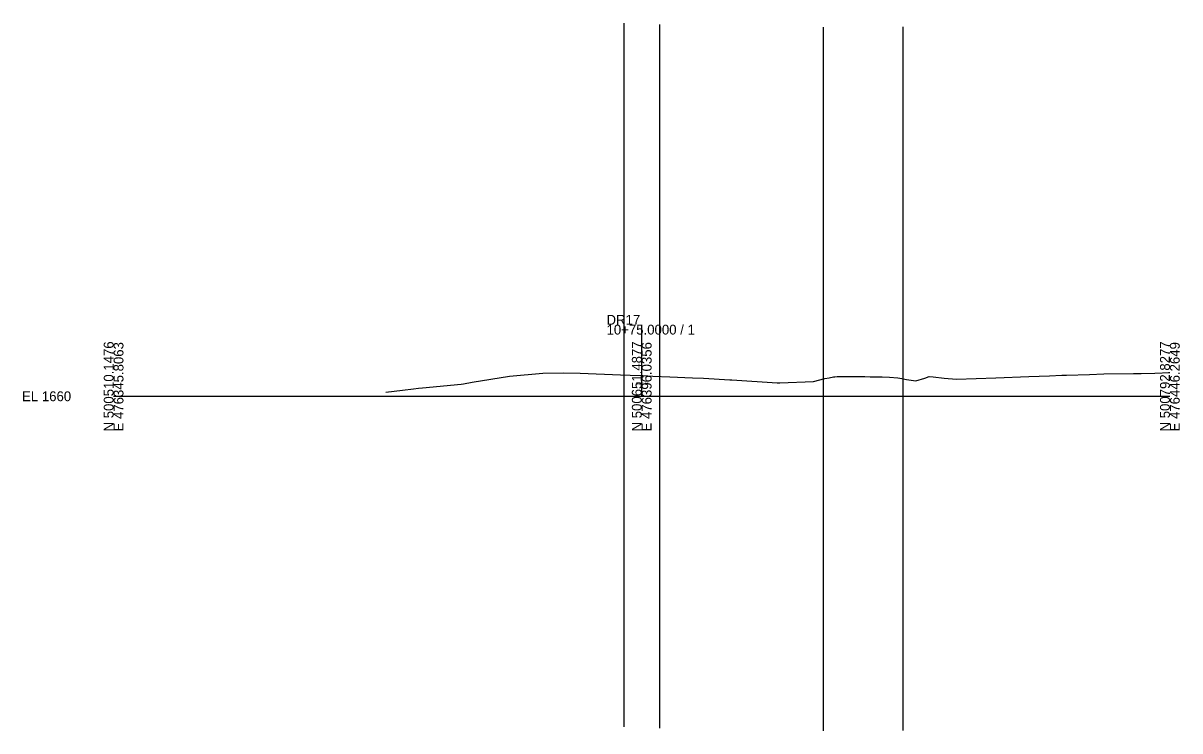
# Model space of a CAD drawing. Extents: x -26 to 303, y -96 to 3030.
# Drawn here: x -25.7 to 302.8, y 1404.9 to 1606.1 of the extents above; entities that cross this region are included whole.
import ezdxf

# ---------------------------------------------------------------- set-up
doc = ezdxf.new("R2010")
doc.units = 0
for name, color, linetype in [('Exist Cross Section Cell', 7, 'Continuous'), ('Exist XS Center Line Elevation Label', 7, 'Continuous'), ('Exist XS Ground Line', 7, 'Continuous'), ('Scratch_Level_2', 7, 'Continuous')]:
    doc.layers.add(name, color=color, linetype=linetype)

msp = doc.modelspace()

# ---------------------------------------------------------------- linework, layer by layer
at = {"layer": 'Exist Cross Section Cell'}
for p, q in [((150, 1500), (150, 1520.34)), ((0, 1500), (150, 1500)), ((150, 1500), (300, 1500))]:
    msp.add_line(p, q, dxfattribs=at)
at = {"layer": 'Exist XS Ground Line'}
msp.add_lwpolyline([(77.33, 1501.17), (82.1, 1501.69), (85.21, 1502.16), (86.57, 1502.28), (87.77, 1502.43), (98.67, 1503.49), (99.42, 1503.55), (101.84, 1503.98), (112.44, 1505.69), (121.89, 1506.55), (127.65, 1506.67), (132.47, 1506.61), (144, 1506.1), (146.67, 1506.01), (150, 1505.93), (150.32, 1505.92), (153.18, 1505.74), (157.95, 1505.56), (164.45, 1505.23), (167.54, 1505.11), (175.06, 1504.68), (175.59, 1504.63), (188.42, 1503.86), (189.23, 1503.85), (198.79, 1504.18), (201.98, 1505.01), (203.23, 1505.29), (204.44, 1505.55), (204.85, 1505.57), (205.53, 1505.6), (206.28, 1505.63), (206.98, 1505.66), (208.54, 1505.66), (209.64, 1505.66), (211.93, 1505.65), (212.37, 1505.64), (213.39, 1505.62), (214.91, 1505.55), (216.01, 1505.53), (217.56, 1505.51), (218.29, 1505.48), (220.35, 1505.4), (222.72, 1505.29), (223.87, 1505.05), (225.21, 1504.78), (225.89, 1504.65), (227.85, 1504.37), (230.36, 1505.15), (231.61, 1505.6), (232.73, 1505.48), (235.91, 1505.15), (239.44, 1504.83), (250.54, 1505.26), (259.98, 1505.64), (265.85, 1505.85), (269.35, 1505.98), (270.6, 1506.04), (277.19, 1506.23), (281.21, 1506.34), (289.68, 1506.45), (291.83, 1506.47), (295.72, 1506.61), (300, 1506.78)], dxfattribs=at)
at = {"layer": 'Scratch_Level_2'}
for p, q in [((144.94, 1606.07), (144.94, 1406.07)), ((155.06, 1605.67), (155.06, 1405.67)), ((201.53, 1604.89), (201.53, 1404.89)), ((224.13, 1605), (224.13, 1405))]:
    msp.add_line(p, q, dxfattribs=at)

# ---------------------------------------------------------------- texts
at = {"layer": 'Exist Cross Section Cell'}
for s, p in [('DR17', (140, 1520.34)), ('10+75.0000 / 1', (140, 1517.54)), ('EL 1660', (-26, 1498.6))]:
    msp.add_text(s, height=2.8, dxfattribs=at).set_placement(p)
for s, p in [('N 500510.1476', (0, 1490)), ('E 476345.8063', (2.8, 1490)), ('N 500651.4877', (150, 1490)), ('E 476396.0356', (152.8, 1490)), ('N 500792.8277', (300, 1490)), ('E 476446.2649', (302.8, 1490))]:
    msp.add_text(s, height=2.8, rotation=90, dxfattribs=at).set_placement(p)
at = {"layer": 'Exist XS Center Line Elevation Label'}
msp.add_text('1665.93', height=0.75, dxfattribs=at).set_placement((148.23, 1503.18))

doc.saveas('drawing.dxf')
